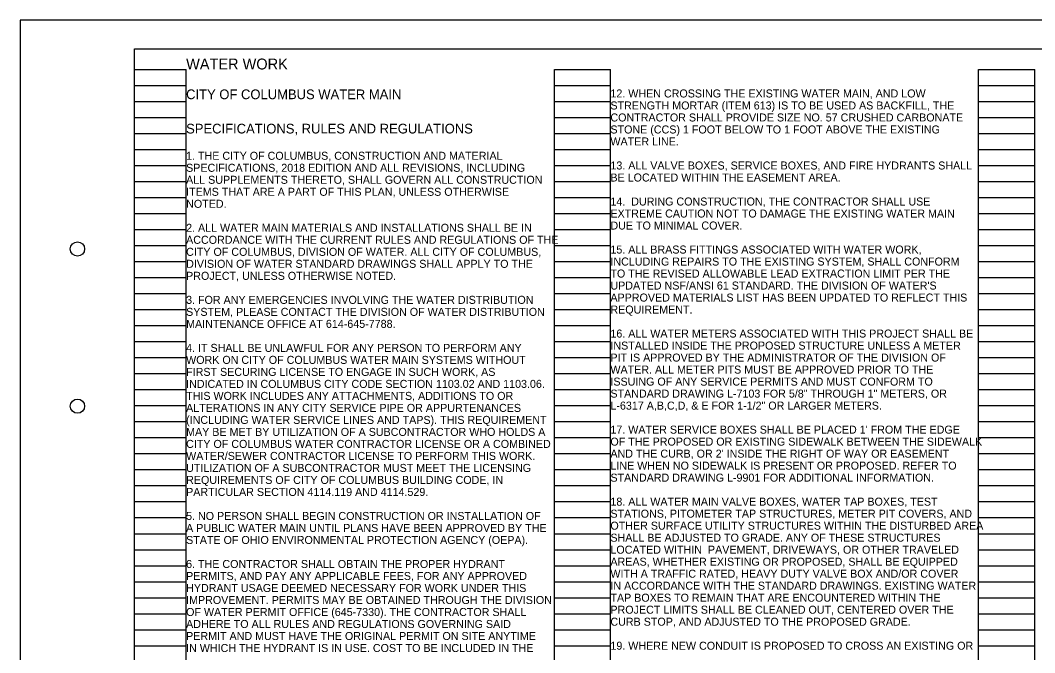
# Model space of a CAD drawing. Extents: x 0 to 34, y 0 to 22.
# Drawn here: x 0 to 17.74, y 10.94 to 22 of the extents above; entities that cross this region are included whole.
import ezdxf

# ---------------------------------------------------------------- set-up
doc = ezdxf.new("R2010")
doc.units = 0
for name, color, linetype in [('SC_Scratch1', 7, 'Continuous'), ('SH_Border', 7, 'Continuous'), ('SH_Cut_Line', 7, 'Continuous'), ('SH_Text', 7, 'Continuous'), ('TX_P_1', 7, 'Continuous')]:
    doc.layers.add(name, color=color, linetype=linetype)

msp = doc.modelspace()

# ---------------------------------------------------------------- linework, layer by layer
at = {"layer": 'SC_Scratch1'}
for p, q in [((2, 0.98), (2, 21.14)), ((2, 21.14), (2.9, 21.14)), ((2.9, 0.98), (2.9, 21.14)), ((9.34, 0.98), (9.34, 21.14)), ((9.34, 21.14), (10.32, 21.14)), ((10.32, 0.98), (10.32, 21.14)), ((16.76, 0.98), (16.76, 21.14)), ((16.76, 21.14), (17.74, 21.14)), ((17.74, 0.98), (17.74, 21.14)), ((2, 20.86), (2.9, 20.86)), ((9.34, 20.86), (10.32, 20.86)), ((16.76, 20.86), (17.74, 20.86)), ((2, 20.58), (2.9, 20.58)), ((9.34, 20.58), (10.32, 20.58)), ((16.76, 20.58), (17.74, 20.58)), ((2, 20.3), (2.9, 20.3)), ((9.34, 20.3), (10.32, 20.3)), ((16.76, 20.3), (17.74, 20.3)), ((2, 20.02), (2.9, 20.02)), ((9.34, 20.02), (10.32, 20.02)), ((16.76, 20.02), (17.74, 20.02)), ((2, 19.74), (2.9, 19.74)), ((9.34, 19.74), (10.32, 19.74)), ((16.76, 19.74), (17.74, 19.74)), ((2, 19.46), (2.9, 19.46)), ((9.34, 19.46), (10.32, 19.46)), ((16.76, 19.46), (17.74, 19.46)), ((2, 19.18), (2.9, 19.18)), ((9.34, 19.18), (10.32, 19.18)), ((16.76, 19.18), (17.74, 19.18)), ((2, 18.9), (2.9, 18.9)), ((9.34, 18.9), (10.32, 18.9)), ((16.76, 18.9), (17.74, 18.9)), ((2, 18.62), (2.9, 18.62)), ((9.34, 18.62), (10.32, 18.62)), ((16.76, 18.62), (17.74, 18.62)), ((2, 18.34), (2.9, 18.34)), ((9.34, 18.34), (10.32, 18.34)), ((16.76, 18.34), (17.74, 18.34)), ((2, 18.06), (2.9, 18.06)), ((9.34, 18.06), (10.32, 18.06)), ((16.76, 18.06), (17.74, 18.06)), ((2, 17.78), (2.9, 17.78)), ((9.34, 17.78), (10.32, 17.78)), ((16.76, 17.78), (17.74, 17.78)), ((2, 17.5), (2.9, 17.5)), ((9.34, 17.5), (10.32, 17.5)), ((16.76, 17.5), (17.74, 17.5)), ((2, 17.22), (2.9, 17.22)), ((9.34, 17.22), (10.32, 17.22)), ((16.76, 17.22), (17.74, 17.22)), ((2, 16.94), (2.9, 16.94)), ((9.34, 16.94), (10.32, 16.94)), ((16.76, 16.94), (17.74, 16.94)), ((2, 16.66), (2.9, 16.66)), ((9.34, 16.66), (10.32, 16.66)), ((16.76, 16.66), (17.74, 16.66)), ((2, 16.38), (2.9, 16.38)), ((9.34, 16.38), (10.32, 16.38)), ((16.76, 16.38), (17.74, 16.38)), ((2, 16.1), (2.9, 16.1)), ((9.34, 16.1), (10.32, 16.1)), ((16.76, 16.1), (17.74, 16.1)), ((2, 15.82), (2.9, 15.82)), ((9.34, 15.82), (10.32, 15.82)), ((16.76, 15.82), (17.74, 15.82)), ((2, 15.54), (2.9, 15.54)), ((9.34, 15.54), (10.32, 15.54)), ((16.76, 15.54), (17.74, 15.54)), ((2, 15.26), (2.9, 15.26)), ((9.34, 15.26), (10.32, 15.26)), ((16.76, 15.26), (17.74, 15.26)), ((2, 14.98), (2.9, 14.98)), ((9.34, 14.98), (10.32, 14.98)), ((16.76, 14.98), (17.74, 14.98)), ((2, 14.7), (2.9, 14.7)), ((9.34, 14.7), (10.32, 14.7)), ((16.76, 14.7), (17.74, 14.7)), ((2, 14.42), (2.9, 14.42)), ((9.34, 14.42), (10.32, 14.42)), ((16.76, 14.42), (17.74, 14.42)), ((2, 14.14), (2.9, 14.14)), ((9.34, 14.14), (10.32, 14.14)), ((16.76, 14.14), (17.74, 14.14)), ((2, 13.86), (2.9, 13.86)), ((9.34, 13.86), (10.32, 13.86)), ((16.76, 13.86), (17.74, 13.86)), ((2, 13.58), (2.9, 13.58)), ((9.34, 13.58), (10.32, 13.58)), ((16.76, 13.58), (17.74, 13.58)), ((2, 13.3), (2.9, 13.3)), ((9.34, 13.3), (10.32, 13.3)), ((16.76, 13.3), (17.74, 13.3)), ((2, 13.02), (2.9, 13.02)), ((9.34, 13.02), (10.32, 13.02)), ((16.76, 13.02), (17.74, 13.02)), ((2, 12.74), (2.9, 12.74)), ((9.34, 12.74), (10.32, 12.74)), ((16.76, 12.74), (17.74, 12.74)), ((2, 12.46), (2.9, 12.46)), ((9.34, 12.46), (10.32, 12.46)), ((16.76, 12.46), (17.74, 12.46)), ((2, 12.18), (2.9, 12.18)), ((9.34, 12.18), (10.32, 12.18)), ((16.76, 12.18), (17.74, 12.18)), ((2, 11.9), (2.9, 11.9)), ((9.34, 11.9), (10.32, 11.9)), ((16.76, 11.9), (17.74, 11.9)), ((2, 11.62), (2.9, 11.62)), ((9.34, 11.62), (10.32, 11.62)), ((16.76, 11.62), (17.74, 11.62)), ((2, 11.34), (2.9, 11.34)), ((9.34, 11.34), (10.32, 11.34)), ((16.76, 11.34), (17.74, 11.34)), ((2, 11.06), (2.9, 11.06)), ((9.34, 11.06), (10.32, 11.06)), ((16.76, 11.06), (17.74, 11.06))]:
    msp.add_line(p, q, dxfattribs=at)
at = {"layer": 'SH_Border'}
msp.add_lwpolyline([(2, 21.5), (33.5, 21.5), (33.5, 0.5), (2, 0.5)], close=True, dxfattribs=at)
for centre in [(1, 18), (1, 15.25)]:
    msp.add_circle(centre, 0.125, dxfattribs=at)
at = {"layer": 'SH_Cut_Line'}
msp.add_lwpolyline([(0, 0), (34, 0), (34, 22), (0, 22)], close=True, dxfattribs=at)

# ---------------------------------------------------------------- texts
at = {"layer": 'SH_Text'}
for s, p in [('12. WHEN CROSSING THE EXISTING WATER MAIN, AND LOW ', (10.32, 20.65)), ('STRENGTH MORTAR (ITEM 613) IS TO BE USED AS BACKFILL, THE ', (10.32, 20.44)), ('CONTRACTOR SHALL PROVIDE SIZE NO. 57 CRUSHED CARBONATE ', (10.32, 20.23)), ('STONE (CCS) 1 FOOT BELOW TO 1 FOOT ABOVE THE EXISTING ', (10.32, 20.02)), ('WATER LINE.', (10.32, 19.81)), ('1. THE CITY OF COLUMBUS, CONSTRUCTION AND MATERIAL ', (2.9, 19.56)), ('13. ALL VALVE BOXES, SERVICE BOXES, AND FIRE HYDRANTS SHALL ', (10.32, 19.39)), ('SPECIFICATIONS, 2018 EDITION AND ALL REVISIONS, INCLUDING ', (2.9, 19.35)), ('ALL SUPPLEMENTS THERETO, SHALL GOVERN ALL CONSTRUCTION ', (2.9, 19.14)), ('BE LOCATED WITHIN THE EASEMENT AREA.  ', (10.32, 19.18)), ('ITEMS THAT ARE A PART OF THIS PLAN, UNLESS OTHERWISE ', (2.9, 18.93)), ('NOTED.', (2.9, 18.72)), ('14.  DURING CONSTRUCTION, THE CONTRACTOR SHALL USE ', (10.32, 18.76)), ('EXTREME CAUTION NOT TO DAMAGE THE EXISTING WATER MAIN ', (10.32, 18.55)), ('DUE TO MINIMAL COVER.', (10.32, 18.34)), ('2. ALL WATER MAIN MATERIALS AND INSTALLATIONS SHALL BE IN ', (2.9, 18.3)), ('ACCORDANCE WITH THE CURRENT RULES AND REGULATIONS OF THE ', (2.9, 18.09)), ('CITY OF COLUMBUS, DIVISION OF WATER. ALL CITY OF COLUMBUS, ', (2.9, 17.88)), ('15. ALL BRASS FITTINGS ASSOCIATED WITH WATER WORK, ', (10.32, 17.92)), ('DIVISION OF WATER STANDARD DRAWINGS SHALL APPLY TO THE ', (2.9, 17.67)), ('INCLUDING REPAIRS TO THE EXISTING SYSTEM, SHALL CONFORM ', (10.32, 17.71)), ('PROJECT, UNLESS OTHERWISE NOTED.', (2.9, 17.46)), ('TO THE REVISED ALLOWABLE LEAD EXTRACTION LIMIT PER THE ', (10.32, 17.5)), ("UPDATED NSF/ANSI 61 STANDARD. THE DIVISION OF WATER'S ", (10.32, 17.29)), ('APPROVED MATERIALS LIST HAS BEEN UPDATED TO REFLECT THIS ', (10.32, 17.08)), ('3. FOR ANY EMERGENCIES INVOLVING THE WATER DISTRIBUTION ', (2.9, 17.04)), ('SYSTEM, PLEASE CONTACT THE DIVISION OF WATER DISTRIBUTION ', (2.9, 16.83)), ('REQUIREMENT. ', (10.32, 16.87)), ('MAINTENANCE OFFICE AT 614-645-7788.', (2.9, 16.62)), ('16. ALL WATER METERS ASSOCIATED WITH THIS PROJECT SHALL BE ', (10.32, 16.45)), ('4. IT SHALL BE UNLAWFUL FOR ANY PERSON TO PERFORM ANY ', (2.9, 16.2)), ('INSTALLED INSIDE THE PROPOSED STRUCTURE UNLESS A METER ', (10.32, 16.24)), ('PIT IS APPROVED BY THE ADMINISTRATOR OF THE DIVISION OF ', (10.32, 16.03)), ('WORK ON CITY OF COLUMBUS WATER MAIN SYSTEMS WITHOUT ', (2.9, 15.99)), ('FIRST SECURING LICENSE TO ENGAGE IN SUCH WORK, AS ', (2.9, 15.78)), ('WATER. ALL METER PITS MUST BE APPROVED PRIOR TO THE ', (10.32, 15.82)), ('INDICATED IN COLUMBUS CITY CODE SECTION 1103.02 AND 1103.06. ', (2.9, 15.57)), ('ISSUING OF ANY SERVICE PERMITS AND MUST CONFORM TO ', (10.32, 15.61)), ('THIS WORK INCLUDES ANY ATTACHMENTS, ADDITIONS TO OR ', (2.9, 15.36)), ('STANDARD DRAWING L-7103 FOR 5/8" THROUGH 1" METERS, OR ', (10.32, 15.4)), ('ALTERATIONS IN ANY CITY SERVICE PIPE OR APPURTENANCES ', (2.9, 15.15)), ('L-6317 A,B,C,D, & E FOR 1-1/2" OR LARGER METERS.', (10.32, 15.19)), ('(INCLUDING WATER SERVICE LINES AND TAPS). THIS REQUIREMENT ', (2.9, 14.94)), ("17. WATER SERVICE BOXES SHALL BE PLACED 1' FROM THE EDGE ", (10.32, 14.77)), ('MAY BE MET BY UTILIZATION OF A SUBCONTRACTOR WHO HOLDS A ', (2.9, 14.73)), ('CITY OF COLUMBUS WATER CONTRACTOR LICENSE OR A COMBINED ', (2.9, 14.52)), ('OF THE PROPOSED OR EXISTING SIDEWALK BETWEEN THE SIDEWALK ', (10.32, 14.56)), ('WATER/SEWER CONTRACTOR LICENSE TO PERFORM THIS WORK. ', (2.9, 14.31)), ("AND THE CURB, OR 2' INSIDE THE RIGHT OF WAY OR EASEMENT ", (10.32, 14.35)), ('UTILIZATION OF A SUBCONTRACTOR MUST MEET THE LICENSING ', (2.9, 14.1)), ('LINE WHEN NO SIDEWALK IS PRESENT OR PROPOSED. REFER TO ', (10.32, 14.14)), ('REQUIREMENTS OF CITY OF COLUMBUS BUILDING CODE, IN ', (2.9, 13.89)), ('STANDARD DRAWING L-9901 FOR ADDITIONAL INFORMATION.', (10.32, 13.93)), ('PARTICULAR SECTION 4114.119 AND 4114.529.', (2.9, 13.68)), ('18. ALL WATER MAIN VALVE BOXES, WATER TAP BOXES, TEST ', (10.32, 13.51)), ('5. NO PERSON SHALL BEGIN CONSTRUCTION OR INSTALLATION OF ', (2.9, 13.26)), ('STATIONS, PITOMETER TAP STRUCTURES, METER PIT COVERS, AND ', (10.32, 13.3)), ('A PUBLIC WATER MAIN UNTIL PLANS HAVE BEEN APPROVED BY THE ', (2.9, 13.05)), ('OTHER SURFACE UTILITY STRUCTURES WITHIN THE DISTURBED AREA ', (10.32, 13.09)), ('STATE OF OHIO ENVIRONMENTAL PROTECTION AGENCY (OEPA).', (2.9, 12.84)), ('SHALL BE ADJUSTED TO GRADE. ANY OF THESE STRUCTURES ', (10.32, 12.88)), ('LOCATED WITHIN  PAVEMENT, DRIVEWAYS, OR OTHER TRAVELED ', (10.32, 12.67)), ('AREAS, WHETHER EXISTING OR PROPOSED, SHALL BE EQUIPPED ', (10.32, 12.46)), ('6. THE CONTRACTOR SHALL OBTAIN THE PROPER HYDRANT ', (2.9, 12.42)), ('PERMITS, AND PAY ANY APPLICABLE FEES, FOR ANY APPROVED ', (2.9, 12.21)), ('WITH A TRAFFIC RATED, HEAVY DUTY VALVE BOX AND/OR COVER ', (10.32, 12.25)), ('HYDRANT USAGE DEEMED NECESSARY FOR WORK UNDER THIS ', (2.9, 12)), ('IN ACCORDANCE WITH THE STANDARD DRAWINGS. EXISTING WATER ', (10.32, 12.04)), ('IMPROVEMENT. PERMITS MAY BE OBTAINED THROUGH THE DIVISION ', (2.9, 11.79)), ('TAP BOXES TO REMAIN THAT ARE ENCOUNTERED WITHIN THE ', (10.32, 11.83)), ('OF WATER PERMIT OFFICE (645-7330). THE CONTRACTOR SHALL ', (2.9, 11.58)), ('PROJECT LIMITS SHALL BE CLEANED OUT, CENTERED OVER THE ', (10.32, 11.62)), ('CURB STOP, AND ADJUSTED TO THE PROPOSED GRADE.', (10.32, 11.41)), ('ADHERE TO ALL RULES AND REGULATIONS GOVERNING SAID ', (2.9, 11.37)), ('PERMIT AND MUST HAVE THE ORIGINAL PERMIT ON SITE ANYTIME ', (2.9, 11.16)), ('IN WHICH THE HYDRANT IS IN USE. COST TO BE INCLUDED IN THE ', (2.9, 10.95)), ('19. WHERE NEW CONDUIT IS PROPOSED TO CROSS AN EXISTING OR ', (10.32, 10.99))]:
    msp.add_text(s, height=0.14, dxfattribs=at).set_placement(p)
at = {"layer": 'TX_P_1'}
for s, height, p in [('WATER WORK', 0.19, (2.9, 21.14)), ('CITY OF COLUMBUS WATER MAIN ', 0.17, (2.9, 20.62)), ('SPECIFICATIONS, RULES AND REGULATIONS', 0.17, (2.9, 20.02))]:
    msp.add_text(s, height=height, dxfattribs=at).set_placement(p)

doc.saveas('drawing.dxf')
